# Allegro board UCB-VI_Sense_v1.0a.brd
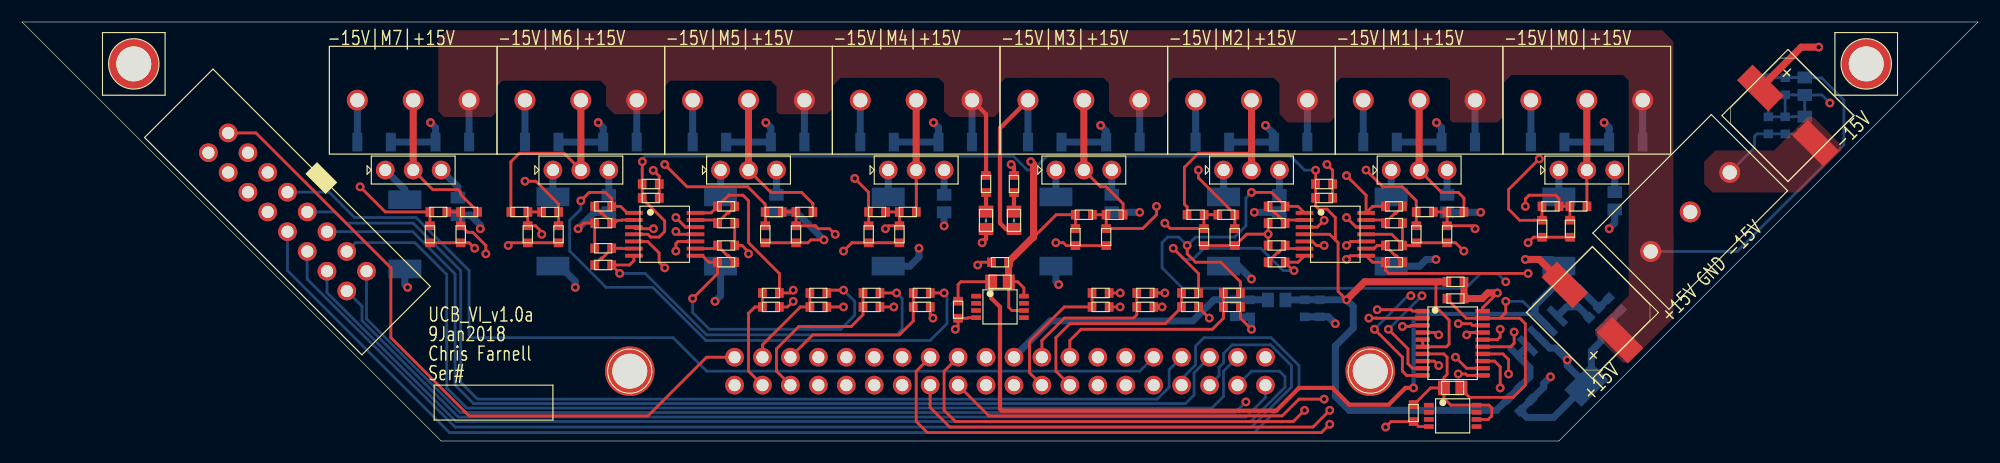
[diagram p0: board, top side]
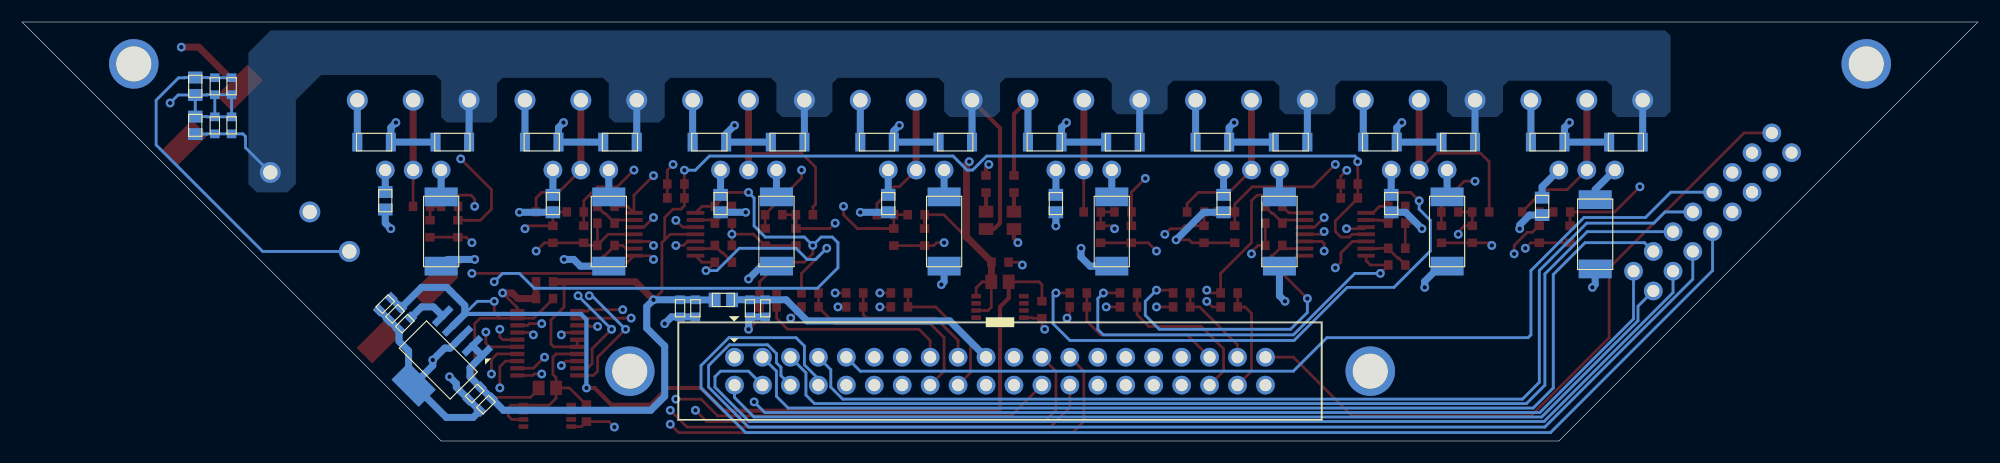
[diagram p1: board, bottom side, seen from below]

Outline 177.8 x 38.1 mm; copper layers: TOP, LAYER_2, LAYER_3, BOTTOM. Coordinates in mm from the lower left corner of the outline.
Outline path: 0,38.1 38.1,0 139.7,0 177.8,38.1 0,38.1

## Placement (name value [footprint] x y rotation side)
ADC1  AD7928BRUZ  [20-TSSOP]  130.05 8.89 0 top
C1  10uF  [C_1206]  145.8 27.18 180 bottom
C2  10uF  [C_1206]  130.56 27.18 180 bottom
C3  10uF  [C_1206]  115.32 27.18 180 bottom
C4  10uF  [C_1206]  100.08 27.18 180 bottom
C5  10uF  [C_1206]  84.84 27.18 180 bottom
C6  10uF  [C_1206]  69.6 27.18 180 bottom
C7  10uF  [C_1206]  54.36 27.18 180 bottom
C8  10uF  [C_1206]  39.12 27.18 180 bottom
C9  22uF  [C_0805]  162.05 32.26 270 bottom
C10  1uF  [C_0603]  160.27 32.26 270 bottom
C11  0.1uF  [C_0603]  158.75 32.26 270 bottom
C12  10uF  [C_1206]  138.68 27.18 180 bottom
C13  10uF  [C_1206]  123.44 27.18 180 bottom
C14  10uF  [C_1206]  108.2 27.18 180 bottom
C15  10uF  [C_1206]  92.96 27.18 180 bottom
C16  10uF  [C_1206]  77.72 27.18 180 bottom
C17  10uF  [C_1206]  62.48 27.18 180 bottom
C18  10uF  [C_1206]  47.24 27.18 180 bottom
C19  10uF  [C_1206]  32 27.18 180 bottom
C20  220uF  [EEE-FK-F]  142.75 11.68 135 top
C21  220uF  [EEE-FK-F]  160.53 29.59 315 top
C22  22uF  [C_0805]  162.05 28.7 270 bottom
C23  1uF  [C_0603]  160.27 28.7 270 bottom
C24  0.1uF  [C_0603]  158.75 28.7 270 bottom
C25  1uF  [C_0603]  110.24 12.06 270 bottom
C26  0.1uF  [C_0603]  111.63 12.06 270 bottom
C27  1uF  [C_0603]  116.59 12.06 270 bottom
C28  1uF  [C_0603]  85.09 11.94 270 top
C29  0.1uF  [C_0603]  117.98 12.06 270 bottom
C30  1uF  [C_0603]  88.9 16.26 0 top
C31  1uF  [C_0603]  135.64 3.3 315 bottom
C32  0.1uF  [C_0603]  136.65 4.32 315 bottom
C33  10nF  [C_0603]  143 10.67 315 bottom
C34  0.1uF  [C_0603]  143.89 11.56 315 bottom
C35  1uF  [C_0603]  144.78 12.45 315 bottom
C36  100pF  [C_0603]  140.72 19.3 90 top
C37  0.1uF  [C_0603]  138.18 19.3 270 top
C38  1uF  [C_0603]  130.3 14.48 0 top
C39  1uF  [C_0603]  130.3 12.95 0 top
C40  1uF  [C_0603]  126.49 2.54 90 top
C41  100pF  [C_0603]  129.54 18.8 90 top
C42  0.1uF  [C_0603]  126.75 18.8 270 top
C43  100pF  [C_0603]  107.44 18.54 90 top
C44  0.1uF  [C_0603]  110.24 18.54 270 top
C45  100pF  [C_0603]  98.55 18.54 90 top
C46  0.1uF  [C_0603]  95.76 18.54 270 top
C47  100pF  [C_0603]  79.76 18.8 90 top
C48  0.1uF  [C_0603]  76.96 18.8 270 top
C49  100pF  [C_0603]  70.36 18.8 90 top
C50  0.1uF  [C_0603]  67.56 18.8 270 top
C51  100pF  [C_0603]  45.97 18.8 90 top
C52  0.1uF  [C_0603]  48.77 18.8 270 top
C53  100pF  [C_0603]  39.88 18.8 90 top
C54  0.1uF  [C_0603]  37.08 18.8 270 top
C55  0.1uF  [C_0603]  118.36 22.1 0 top
C56  1uF  [C_0603]  118.36 23.37 0 top
C57  0.1uF  [C_0603]  57.15 22.1 0 top
C58  1uF  [C_0603]  57.15 23.37 0 top
D1  LED-G  [LED_0805-GREEN]  87.63 20.07 90 top
D2  LED-G  [LED_0805-GREEN]  90.17 20.07 90 top
J1  -  [1715734]  151.64 20.83 135 top
J3  SFH11-PBPC-D20-ST-BK  [40-IDC-F_MNT]  88.9 6.35 270 bottom
J4  AWHW 16G-0202-T  [16-IDC-M]  24.13 20.83 225 top
J5  -  [1715734]  142.24 30.99 270 top
J6  -  [1715734]  127 30.99 270 top
J7  -  [1715734]  111.76 30.99 270 top
J8  -  [1715734]  96.52 30.99 270 top
J9  -  [1715734]  81.28 30.99 270 top
J10  -  [1715734]  66.04 30.99 270 top
J11  -  [1715734]  50.8 30.99 270 top
J12  -  [1715734]  35.56 30.99 270 top
JP1  JP3  [J_1X3]  142.24 24.64 90 top
JP2  JP3  [J_1X3]  127 24.64 90 top
JP3  JP3  [J_1X3]  111.76 24.64 90 top
JP4  JP3  [J_1X3]  96.52 24.64 90 top
JP5  JP3  [J_1X3]  81.28 24.64 90 top
JP6  JP3  [J_1X3]  66.04 24.64 90 top
JP7  JP3  [J_1X3]  50.8 24.64 90 top
JP8  JP3  [J_1X3]  35.56 24.64 90 top
L1  220  [L_0805]  114.05 12.83 0 bottom
MECH1  Mech_Hole  [4-40_SCREW]  10.16 34.29 0 top
MECH2  Mech_Hole  [4-40_SCREW]  167.64 34.29 0 top
R1  6.19  [R_2512]  139.7 19.05 90 bottom
R3  1k  [R_0805]  88.9 14.48 0 top
R8  1k  [R_0805]  130.05 4.83 180 top
R9  200k  [R_0603]  141.48 21.34 180 top
R10  200k  [R_0603]  114.05 19.81 0 top
R11  100k  [R_0603]  138.94 21.34 0 top
R12  100k  [R_0603]  114.05 21.34 0 top
R13  2k  [R_0603]  87.63 23.37 270 top
R14  2k  [R_0603]  90.17 23.37 270 top
R15  10k  [R_0603]  109.98 13.46 180 top
R16  15k  [R_0603]  109.98 12.19 0 top
R17  10k  [R_0603]  106.17 13.46 180 top
R18  15k  [R_0603]  106.17 12.19 0 top
R19  200k  [R_0603]  130.3 20.83 180 top
R20  200k  [R_0603]  114.05 17.78 0 top
R21  100k  [R_0603]  127.51 20.83 0 top
R22  100k  [R_0603]  114.05 16.26 0 top
R23  10k  [R_0603]  102.11 13.46 180 top
R24  15k  [R_0603]  102.11 12.19 0 top
R25  200k  [R_0603]  106.68 20.57 0 top
R26  200k  [R_0603]  124.71 17.78 180 top
R27  100k  [R_0603]  109.47 20.57 180 top
R28  100k  [R_0603]  124.71 16.26 180 top
R29  10k  [R_0603]  98.04 13.46 180 top
R30  15k  [R_0603]  98.04 12.19 0 top
R31  200k  [R_0603]  99.31 20.57 180 top
R32  200k  [R_0603]  124.71 19.81 180 top
R33  100k  [R_0603]  96.52 20.57 0 top
R34  100k  [R_0603]  124.71 21.34 180 top
R35  10k  [R_0603]  81.79 13.46 180 top
R36  15k  [R_0603]  81.79 12.19 0 top
R37  200k  [R_0603]  80.52 20.83 180 top
R38  200k  [R_0603]  52.83 19.81 0 top
R39  100k  [R_0603]  77.72 20.83 0 top
R40  100k  [R_0603]  52.83 21.34 0 top
R41  10k  [R_0603]  77.22 13.46 180 top
R42  15k  [R_0603]  77.22 12.19 0 top
R43  200k  [R_0603]  71.12 20.83 180 top
R44  200k  [R_0603]  52.83 17.53 0 top
R45  100k  [R_0603]  68.33 20.83 0 top
R46  100k  [R_0603]  52.83 16 0 top
R47  10k  [R_0603]  72.39 13.46 180 top
R48  15k  [R_0603]  72.39 12.19 0 top
R49  200k  [R_0603]  45.21 20.83 0 top
R50  200k  [R_0603]  64.01 17.78 180 top
R51  100k  [R_0603]  48.01 20.83 180 top
R52  100k  [R_0603]  64.01 16.26 180 top
R53  10k  [R_0603]  68.07 13.46 180 top
R54  15k  [R_0603]  68.07 12.19 0 top
R55  200k  [R_0603]  40.64 20.83 180 top
R56  200k  [R_0603]  64.01 19.81 180 top
R57  100k  [R_0603]  37.85 20.83 0 top
R58  100k  [R_0603]  64.01 21.34 180 top
R59  6.19  [R_2512]  124.46 19.05 90 bottom
R61  6.19  [R_2512]  109.22 19.05 90 bottom
R63  6.19  [R_2512]  93.98 19.05 90 bottom
R65  6.19  [R_2512]  78.74 19.05 90 bottom
R67  6.19  [R_2512]  63.5 19.05 90 bottom
R69  6.19  [R_2512]  48.26 19.05 90 bottom
R71  6.19  [R_2512]  34.8 18.8 90 bottom
R72  140  [R_0805]  144.78 21.84 90 bottom
R73  140  [R_0805]  129.54 21.59 90 bottom
R74  140  [R_0805]  114.3 21.59 90 bottom
R75  140  [R_0805]  99.06 21.59 90 bottom
R76  140  [R_0805]  83.82 21.59 90 bottom
R77  140  [R_0805]  68.58 21.59 90 bottom
R78  140  [R_0805]  53.34 21.59 90 bottom
R79  140  [R_0805]  39.62 21.34 90 bottom
U1  LT1009CZ  [8-MSOP]  88.9 12.19 0 top
U2  TPS79533  [SOT-223-6]  139.95 7.37 135 bottom
U4  LT1009CZ  [8-MSOP]  130.05 2.29 0 top
U5  OPA4322AIPWR  [OPA4332_14-TSSOP]  119.38 18.8 0 top
U6  OPA4322AIPWR  [OPA4332_14-TSSOP]  58.42 18.8 0 top

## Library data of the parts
ADC1 = AD7928BRUZ
C1-C19 C22-C58 = CAP NP
C20 C21 = CAP P
D1 D2 = LED
J1 J5-J12 = Connector-3
J3 = Header_2x20
J4 = Header_2x8
JP1-JP8 = JP3
L1 = Ind
MECH1 MECH2 = Mech_Hole
R1 R3 R8-R59 R61 R63 R65 R67 R69 R71-R79 = R-Standard
U1 U4 = LT1009CZ
U2 = TPS795
U5 U6 = OPA4322AIPWR

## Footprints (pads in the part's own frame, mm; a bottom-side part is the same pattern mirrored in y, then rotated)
4-40_SCREW
  round 4.5 hole 3.175: 1(0,0)
8-MSOP
  rect 0.889x0.42 smd: 1(-2.17,0.975) 2(-2.17,0.325) 3(-2.17,-0.325) 4(-2.17,-0.975) 5(2.17,-0.975) 6(2.17,-0.325) 7(2.17,0.325) 8(2.17,0.975)
16-IDC-M
  round 1.7 hole 1.1: 1(-1.27,8.89) 2(1.27,8.89) 3(-1.27,6.35) 4(1.27,6.35) 5(-1.27,3.81) 6(1.27,3.81) 7(-1.27,1.27) 8(1.27,1.27) 9(-1.27,-1.27) 10(1.27,-1.27) 11(-1.27,-3.81) 12(1.27,-3.81) 13(-1.27,-6.35) 14(1.27,-6.35) 15(-1.27,-8.89) 16(1.27,-8.89)
20-TSSOP
  rect 1.3x0.4 smd: 1(-2.725,2.925) 2(-2.725,2.275) 3(-2.725,1.625) 4(-2.725,0.975) 5(-2.725,0.325) 6(-2.725,-0.325) 7(-2.725,-0.975) 8(-2.725,-1.625) 9(-2.725,-2.275) 10(-2.725,-2.925) 11(2.725,-2.925) 12(2.725,-2.275) 13(2.725,-1.625) 14(2.725,-0.975) 15(2.725,-0.325) 16(2.725,0.325) 17(2.725,0.975) 18(2.725,1.625) 19(2.725,2.275) 20(2.725,2.925)
40-IDC-F_MNT
  round 4.5 hole 3.175: (0,-33.655) (0,33.655)
  round 1.7 hole 1.1: 1(-1.27,-24.13) 2(1.27,-24.13) 3(-1.27,-21.59) 4(1.27,-21.59) 5(-1.27,-19.05) 6(1.27,-19.05) 7(-1.27,-16.51) 8(1.27,-16.51) 9(-1.27,-13.97) 10(1.27,-13.97) 11(-1.27,-11.43) 12(1.27,-11.43) 13(-1.27,-8.89) 14(1.27,-8.89) 15(-1.27,-6.35) 16(1.27,-6.35) 17(-1.27,-3.81) 18(1.27,-3.81) 19(-1.27,-1.27) 20(1.27,-1.27) 21(-1.27,1.27) 22(1.27,1.27) 23(-1.27,3.81) 24(1.27,3.81) 25(-1.27,6.35) 26(1.27,6.35) 27(-1.27,8.89) 28(1.27,8.89) 29(-1.27,11.43) 30(1.27,11.43) 31(-1.27,13.97) 32(1.27,13.97) 33(-1.27,16.51) 34(1.27,16.51) 35(-1.27,19.05) 36(1.27,19.05) 37(-1.27,21.59) 38(1.27,21.59) 39(-1.27,24.13) 40(1.27,24.13)
1715734
  round 1.9 hole 1.3: 1(0,5.08) 2(0,0) 3(0,-5.08)
C_0603
  rect 0.787x0.864 smd: 1(-0.775,0) 2(0.775,0)
C_0805
  rect 1.08x1.321 smd: 1(-0.794,0) 2(0.794,0)
C_1206
  rect 0.914x1.702 smd: 1(-1.524,0) 2(1.524,0)
EEE-FK-F
  rect 4x2 smd: 1(-3.55,0) 2(3.55,0)
J_1X3
  round 1.7 hole 1.1: 1(0,2.54) 2(0,0) 3(0,-2.54)
L_0805
  rect 1.08x1.321 smd: 1(-0.794,0) 2(0.794,0)
LED_0805-GREEN
  rect 1.08x1.321 smd: 1(-0.794,0) 2(0.794,0)
OPA4332_14-TSSOP
  rect 1.6x0.35 smd: 1(-2.8,1.95) 2(-2.8,1.3) 3(-2.8,0.65) 4(-2.8,0) 5(-2.8,-0.65) 6(-2.8,-1.3) 7(-2.8,-1.95) 8(2.8,-1.95) 9(2.8,-1.3) 10(2.8,-0.65) 11(2.8,0) 12(2.8,0.65) 13(2.8,1.3) 14(2.8,1.95)
R_0603
  rect 0.787x0.864 smd: 1(-0.775,0) 2(0.775,0)
R_0805
  rect 1.08x1.321 smd: 1(-0.794,0) 2(0.794,0)
R_2512
  rect 1.7x3 smd: 1(-3.15,0) 2(3.15,0)
SOT-223-6
  rect 2.2x0.6 smd: 1(3.1,-2.54) 2(3.1,-1.27) 3(3.1,0) 4(3.1,1.27) 5(3.1,2.54)
  rect 2.2x3.5 smd: 6(-3.175,0)

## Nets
2V5_REF: C30.2 C37.1 C42.1 C44.1 C46.1 C48.1 C50.1 C52.1 C54.1 R3.2 R11.1 R21.1 R27.1 R33.1 R39.1 R45.1 R51.1 R57.1 U1.6(V+.) U1.8(V+)
3V3: ADC1.19(VDRIVE) C28.1 C34.1 C35.1 C39.1 R3.1 R8.1 U2.4(VOUT)
5V0: ADC1.5(AVDD) ADC1.6(AVDD.) C27.1 C29.1 C31.1 C32.1 C38.1 C55.1 C56.1 C57.1 C58.1 L1.2 U2.1(EN) U2.2(VIN) U5.4(V+) U6.4(V+)
5V_IDC: C25.1 C26.1 J3.19 J3.39 J4.15 L1.1
+15V: C1.1 C2.1 C3.1 C4.1 C5.1 C6.1 C7.1 C8.1 C9.1 C10.1 C11.1 C20.1 J1.1(P1) J5.1(P1) J6.1(P1) J7.1(P1) J8.1(P1) J9.1(P1) J10.1(P1) J11.1(P1) J12.1(P1) R13.1
-15V: C12.2 C13.2 C14.2 C15.2 C16.2 C17.2 C18.2 C19.2 C21.2 C22.2 C23.2 C24.2 D2.1(CATHODE) J1.3(P3) J5.3(P3) J6.3(P3) J7.3(P3) J8.3(P3) J9.3(P3) J10.3(P3) J11.3(P3) J12.3(P3)
GND: ADC1.4(AGND) ADC1.8(AGND.) ADC1.17(AGND..) ADC1.20(AGND...) C1.2 C2.2 C3.2 C4.2 C5.2 C6.2 C7.2 C8.2 C9.2 C10.2 C11.2 C12.1 C13.1 C14.1 C15.1 C16.1 C17.1 C18.1 C19.1 C20.2 C21.1 C22.1 C23.1 C24.1 C25.2 C26.2 C27.2 C28.2 C29.2 C30.1 C31.2 C32.2 C33.2 C34.2 C35.2 C36.1 C37.2 C38.2 C39.2 C40.1 C41.1 C42.2 C43.1 C44.2 C45.1 C46.2 C47.1 C48.2 C49.1 C50.2 C51.1 C52.2 C53.1 C54.2 C55.2 C56.2 C57.2 C58.2 D1.1(CATHODE) J1.2(P2) J3.20 J3.40 J4.16 R1.1 R10.1 R14.1 R16.2 R18.2 R20.1 R24.2 R26.1 R30.2 R32.1 R36.2 R38.1 R42.2 R44.1 R48.2 R50.1 R54.2 R56.1 R59.1 R61.1 R63.1 R65.1 R67.1 R69.1 R71.1 R72.1 R73.1 R74.1 R75.1 R76.1 R77.1 R78.1 R79.1 U1.4(GND) U2.3(GND) U2.6(GND.) U4.4(GND) U5.11(V-) U6.11(V-)
IDC_ADC-0: J3.15 R15.2 R16.1
IDC_ADC-1: J3.16 R17.2 R18.1
IDC_ADC-2: J3.17 R23.2 R24.1
IDC_ADC-3: J3.18 R29.2 R30.1
IDC_ADC-4: J3.35 R35.2 R36.1
IDC_ADC-5: J3.36 R41.2 R42.1
IDC_ADC-6: J3.37 R47.2 R48.1
IDC_ADC-7: J3.38 R53.2 R54.1
IDC_IO-1: J3.1 J4.1
IDC_IO-2: J3.2 J4.2
IDC_IO-3: J3.3 J4.3
IDC_IO-4: J3.4 J4.4
IDC_IO-5: J3.5 J4.5
IDC_IO-6: J3.6 J4.6
IDC_IO-7: J3.7 J4.7
IDC_IO-8: J3.8 J4.8
IDC_IO-9: J3.9 J4.9
IDC_IO-10: J3.10 J4.10
IDC_IO-11: J3.11 J4.11
IDC_IO-12: J3.12 J4.12
IDC_IO-13: J3.13 J4.13
IDC_IO-14: J3.14 J4.14
MEA_0: J5.2(P2) JP1.2 R9.1
MEA_1: J6.2(P2) JP2.2 R19.1
MEA_2: J7.2(P2) JP3.2 R25.1
MEA_3: J8.2(P2) JP4.2 R31.1
MEA_4: J9.2(P2) JP5.2 R37.1
MEA_5: J10.2(P2) JP6.2 R43.1
MEA_6: J11.2(P2) JP7.2 R49.1
MEA_7: J12.2(P2) JP8.2 R55.1
SPI-ADC_5V-CH0: ADC1.16(VIN0) R12.2 R15.1 U5.1(OUT)
SPI-ADC_5V-CH1: ADC1.15(VIN1) R17.1 R22.2 U5.7(OUT)
SPI-ADC_5V-CH2: ADC1.14(VIN2) R23.1 R28.2 U5.8(OUT)
SPI-ADC_5V-CH3: ADC1.13(VIN3) R29.1 R34.2 U5.14(OUT)
SPI-ADC_5V-CH4: ADC1.12(VIN4) R35.1 R40.2 U6.1(OUT)
SPI-ADC_5V-CH5: ADC1.11(VIN5) R41.1 R46.2 U6.7(OUT)
SPI-ADC_5V-CH6: ADC1.10(VIN6) R47.1 R52.2 U6.8(OUT)
SPI-ADC_5V-CH7: ADC1.9(VIN7) R53.1 R58.2 U6.14(OUT)
SPI-ADC_CS: ADC1.3(CS) J3.24
SPI-ADC_DIN: ADC1.2(DIN) J3.25
SPI-ADC_DOUT: ADC1.18(DOUT) J3.26
SPI-ADC_SCLK: ADC1.1(SCLK) J3.23
N365232: ADC1.7(REF_IN) C40.2 R8.2 U4.6(V+.) U4.8(V+)
N367140: C36.2 R9.2 R11.2 U5.3(+IN)
N367168: R10.2 R12.1 U5.2(-IN)
N370101: C33.1 U2.5(NR/FB)
N387715: JP1.1 R1.2
N388314: JP1.3 R72.2
N392987: D2.2(ANODE) R14.2
N392991: D1.2(ANODE) R13.2
N402358: C41.2 R19.2 R21.2 U5.5(+IN)
N402362: R20.2 R22.1 U5.6(-IN)
N403154: C43.2 R25.2 R27.2 U5.10(+IN)
N403158: R26.2 R28.1 U5.9(-IN)
N403978: C45.2 R31.2 R33.2 U5.12(+IN)
N403982: R32.2 R34.1 U5.13(-IN)
N404826: C47.2 R37.2 R39.2 U6.3(+IN)
N404830: R38.2 R40.1 U6.2(-IN)
N405710: C49.2 R43.2 R45.2 U6.5(+IN)
N405714: R44.2 R46.1 U6.6(-IN)
N406610: C51.2 R49.2 R51.2 U6.10(+IN)
N406614: R50.2 R52.1 U6.9(-IN)
N407827: C53.2 R55.2 R57.2 U6.12(+IN)
N407831: R56.2 R58.1 U6.13(-IN)
N416291: JP2.1 R59.2
N416303: JP2.3 R73.2
N416911: JP3.1 R61.2
N416923: JP3.3 R74.2
N417886: JP4.1 R63.2
N417898: JP4.3 R75.2
N420263: JP5.1 R65.2
N420287: JP5.3 R76.2
N420898: JP6.1 R67.2
N420922: JP6.3 R77.2
N421540: JP7.1 R69.2
N421564: JP7.3 R78.2
N422187: JP8.1 R71.2
N422211: JP8.3 R79.2

Pads without a net: J3 21 22 27 28 29 30 31 32 33 34; MECH1 1; MECH2 1; U1 1 2 3 5 7; U4 1 2 3 5 7

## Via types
v1: diameter 0.8, hole 0.4, TOP to BOTTOM, 122 vias

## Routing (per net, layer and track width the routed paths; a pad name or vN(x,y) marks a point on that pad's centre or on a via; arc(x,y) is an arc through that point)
2V5_REF: length 204.1
  TOP w0.254: 91.95,18.52 94.01,20.57 R33.1 95.76,20.56 C46.1 ; C54.1 37.08,20.82 R57.1 33.02,20.83 v1(30.73,23.11) ; C48.1 76.96,20.82 R39.1 76.95,22.62 v1(75.69,23.88) ; U1.8 91.07,13.92 90.51,14.48 R3.2 89.69,12.16 89.99,11.87 U1.6 ; C50.1 67.56,20.82 R45.1 67.55,21.54 65.98,23.11 60.45,23.11 v1(58.42,25.15) ; C52.1 48.78,19.58 R51.1 48.78,21.54 46.7,23.62 v1(45.72,23.62) ; C42.1 126.75,20.82 R21.1 126.73,21.86 125.48,23.11 123.7,23.11 v1(122.17,24.64) ; R11.1 138.16,20.09 C37.1 137.46,20.08 137.45,20.07 136.14,20.07 135.13,21.08 135.13,22.86 v1(137.92,25.65) ; v1(106.93,24.64) 106.93,23.93 110.25,20.61 R27.1 110.25,19.33 C44.1
  TOP w0.635: R3.2 89.67,14.5 C30.2 89.67,16.29 91.9,18.52 91.95,18.52 91.95,25.15 v1(91.69,25.4)
  LAYER_3 w0.254: v1(45.72,23.62) 45.72,26.67 ; v1(75.69,23.88) 75.69,26.67 ; 57.66,26.67 57.66,25.91 v1(58.42,25.15) ; v1(122.17,24.64) 122.17,26.67 ; v1(106.93,24.64) 106.93,26.67
  LAYER_3 w0.635: v1(137.92,25.65) 136.91,26.67 92.96,26.67 v1(91.69,25.4) 90.42,26.67 32.51,26.67 30.73,24.89 v1(30.73,23.11)
3V3: length 109.9
  TOP w0.254: R8.1 130.84,4.71 131.58,3.97 135.54,3.97 136.65,5.08 136.65,10.67 136.15,11.17 134.38,11.17 ; 134.38,11.17 134.38,11.19 134.87,11.68 v1(134.87,12.7) ; 134.38,11.17 ADC1.19 131.28,11.17 129.53,12.92 C39.1 ; R3.1 85.34,14.48 85.09,14.22 C28.1
  TOP w0.381: R3.1 88.11,12.99 88.9,12.19 88.9,2.92 89.07,2.76 114.01,2.76 116.08,4.83 119.13,4.83 120.65,3.3 124.22,3.3 125.75,4.83 v1(126.49,4.83)
  BOTTOM w0.254: 137.55,11.57 136.42,12.7 v1(134.87,12.7)
  BOTTOM w0.381: 137.55,11.55 127,11.55 126.49,11.05 v1(126.49,4.83)
  BOTTOM w0.635: C35.1 C34.1 141.48,13.97 139.19,13.97 137.55,12.33 137.55,11.55 138.65,10.46 U2.4
5V0: length 147.5
  TOP w0.254: v1(56.39,25.4) 56.39,24.72 56.38,24.71 C58.1 C57.1 56.38,22.06 58.42,20.01 58.42,19.05 57.91,18.54 57.15,18.54 56.9,18.8 U6.4 ; 119.38,18.29 119.63,18.03 119.63,13.6 v1(120.4,12.84) ; 119.38,18.29 119.38,20.32 118.62,21.08 117.89,21.08 117.59,21.39 C55.1 C56.1 v1(117.59,24.63) ; 119.38,18.29 118.87,18.8 U5.4 ; ADC1.5 ADC1.6 129.47,8.56 129.72,8.82 129.72,10.99 128.52,12.19 128.52,14.22 128.78,14.48
  TOP w0.635: v1(120.4,12.84) 122.03,14.48 C38.1
  BOTTOM w0.254: v1(56.39,25.4) 56.39,25.65 56.64,25.91 90.12,25.91 91.39,24.64 91.89,24.64 93.16,25.91 115.32,25.91 116.6,24.63 v1(117.59,24.63)
  BOTTOM w0.635: U2.2 U2.1 137.08,6.65 137.08,5.84 C32.1 C31.1 134.03,2.79 120.65,2.79 119.38,4.06 119.38,8.64 121.01,10.27 121.01,12.22 v1(120.4,12.84) C29.1 C27.1 116.57,12.83 L1.2
5V_IDC: length 122.3
  TOP w0.254: J4.15 21.26,28.01 33.53,15.75 33.53,9.4 40.64,2.29 56.9,2.29 62.23,7.62 J3.39
  LAYER_3 w0.254: J3.19 89.04,6.49 89.04,3.7 88.54,3.2 64.62,3.2 63.5,4.32 63.5,6.35 J3.39
  BOTTOM w0.635: L1.1 113.24,12.84 C26.1 C25.1 108.34,12.84 106.43,10.92 93.47,10.92 J3.19
+15V: length 71.2
  TOP w0.381: R13.1 87.63,29.72 J9.1
  BOTTOM w0.254: J1.1 155.92,17.24 165.61,26.92 165.61,30.99 163.58,33.02 163.02,33.02 162.99,33.05 C9.1 161,33.05 160.99,33.03 C10.1 C11.1
  BOTTOM w0.635: C4.1 J8.1 ; C2.1 J6.1 ; C8.1 J12.1 ; C3.1 J7.1 ; C1.1 J5.1 ; C5.1 J9.1 ; C6.1 J10.1 ; C7.1 J11.1
-15V: length 53.1
  TOP w0.381: J8.3 88.9,28.45 88.9,19.81 89.44,19.27 D2.1
  BOTTOM w0.254: C22.2 161,27.91 160.99,27.93 C23.2 C24.2 157.72,27.93 157.48,27.69 157.48,26.67 J1.3
  BOTTOM w0.635: C17.2 J10.3 ; C15.2 J8.3 ; C16.2 J9.3 ; C13.2 J6.3 ; C19.2 J12.3 ; C12.2 J5.3 ; C14.2 J7.3 ; C18.2 J11.3
GND: length 251.5
  TOP w0.254: v1(82.8,11.18) 82.56,11.42 R36.2 ; v1(72.9,18.29) 71.71,18.29 71.44,18.02 C49.1 C50.2 ; v1(118.62,25.15) 119.14,24.63 C56.2 C55.2 ; v1(74.68,17.27) 75.43,18.02 C48.2 C47.1 ; v1(111.76,10.16) 110.76,11.16 R16.2 ; U5.11 124.51,18.8 125.49,17.82 ; R20.1 v1(113.27,18.81) ; v1(113.27,18.81) 111.32,18.81 110.27,17.77 C44.2 C43.1 ; v1(113.27,18.81) R10.1 ; C54.2 C53.1 40.65,18.02 v1(41.15,17.53) ; R18.2 106.95,12.15 v1(107.92,11.18) ; ADC1.20 132.77,12.12 v1(134.11,13.46) ; v1(131.06,17.27) 130.31,18.02 C41.1 C42.2 126.5,17.78 R26.1 125.49,17.82 ; v1(66.04,17.02) 66.04,17.2 65.46,17.78 R50.1 R56.1 ; R42.2 v1(79.25,12.19) ; U6.11 59.69,18.8 v1(59.44,19.05) ; C45.1 C46.2 94.93,17.77 94.66,18.03 v1(93.98,18.03) ; C36.1 C37.2 137.4,18.53 v1(136.91,18.03) ; v1(128.78,9.65) 128.56,9.87 ADC1.4 ; v1(50.55,19.3) 51.05,19.81 R38.1 R44.1 ; 125.49,17.82 R32.1 ; C30.1 87.12,16.26 v1(86.87,16) ; v1(44.2,17.78) 44.44,18.02 C51.1 C52.2 ; R24.2 v1(103.63,12.19) ; C57.2 C58.2 57.92,24.08 57.39,24.61 v1(57.38,24.61) ; U1.4 86.01,11.22 85.95,11.16 C28.2 85.09,10.41 v1(84.84,10.16) ; R48.2 v1(74.68,12.19) ; ADC1.17 131.53,9.87 v1(131.32,9.65) ; R54.2 69.6,12.19 v1(70.1,12.7) ; U4.4 126.95,1.31 C40.1 124.45,1.77 v1(123.95,1.27) ; v1(128.78,6.86) 128.37,7.26 ADC1.8 ; R30.2 v1(99.82,12.19)
  TOP w0.381: v1(87.27,18.03) 87.63,18.39 D1.1 ; v1(89.92,25.15) 90.17,24.89 R14.1
  TOP w0.635: C38.2 C39.2 132.73,12.95 133.24,13.46 v1(134.11,13.46) ; C21.1 161.73,35.81 v1(163.32,35.81) ; v1(136.65,16.51) 137.92,16.51 C20.2
  BOTTOM w0.254: v1(164.34,30.73) 163.61,31.46 C9.2 ; C23.1 C24.1 C11.2 C10.2 ; C23.1 C10.2 ; C23.1 160.99,29.48 161,29.5 C22.1 C9.2 ; C9.2 161,31.46 160.99,31.48 C10.2
  BOTTOM w0.635: v1(94.23,14.22) 93.98,14.48 R63.1 ; v1(82.86,28.96) 83.31,28.5 C5.2 C16.1 ; v1(138.94,5.84) 138.32,5.23 138.32,4.89 C32.2 C31.2 136.79,2.14 139.22,2.14 U2.6 ; R76.1 v1(83.82,19.56) ; C27.2 C29.2 118.76,11.29 v1(119.38,10.67) ; R1.1 139.09,16.51 v1(136.65,16.51) ; R73.1 v1(132.59,20.8) ; R78.1 52.04,20.8 v1(50.55,19.3) ; R59.1 127.04,15.9 127.65,16.51 v1(128.52,16.51) ; v1(52.38,28.96) 52.83,28.5 C7.2 C18.1 ; v1(98.04,28.7) 98.55,28.19 C4.2 C15.1 ; v1(111.76,14.73) 110.59,15.9 R61.1 ; v1(143.82,28.96) 144.27,28.5 C1.2 C12.1 ; R67.1 63.5,13.21 v1(62.99,12.7) ; v1(37.14,28.96) 37.59,28.5 C8.2 C19.1 ; C35.2 C34.2 C33.2 143.52,10.09 143.52,9.07 142.66,8.2 142.66,5.58 U2.6 ; R77.1 70.39,20.8 v1(72.9,18.29) ; v1(50.29,13.97) 50.29,14.52 48.91,15.9 R69.1 ; R72.1 144.78,19.81 v1(144.27,19.3) ; v1(128.58,28.96) 129.03,28.5 C2.2 C13.1 ; v1(81.53,17.53) 81.53,16.72 80.71,15.9 R65.1 ; U2.6 140.46,6.86 v1(140.46,7.37) 139.38,8.45 138.87,8.45 U2.3 ; R75.1 v1(101.6,20.8) ; v1(41.66,19.3) 41.66,19.64 40.75,20.54 R79.1 ; v1(67.62,28.96) 68.07,28.5 C6.2 C17.1 ; C14.1 C3.2 113.79,27.94 v1(113.03,28.7) ; C25.2 C26.2 111.76,11.16 v1(111.76,10.16) ; R74.1 v1(112.01,20.8) ; R71.1 34.8,14.22 v1(35.05,13.97)
IDC_ADC-0: length 18.6
  TOP w0.254: J3.15 95.25,9.14 96.27,10.16 108.2,10.16 109.21,11.16 R16.1 R15.2
IDC_ADC-1: length 18.7
  TOP w0.254: R17.2 R18.1 105.4,12.15 103.91,10.67 95.25,10.67 93.98,9.4 93.98,6.35 J3.16
IDC_ADC-2: length 13.1
  TOP w0.254: J3.17 92.71,9.14 94.74,11.18 101.03,11.18 101.33,11.48 R24.1 R23.2
IDC_ADC-3: length 12.7
  TOP w0.254: R29.2 R30.1 94.74,12.19 91.58,9.03 91.58,6.21 J3.18
IDC_ADC-4: length 15.1
  TOP w0.254: R35.2 R36.1 81.01,10.91 79.76,9.65 71.88,9.65 J3.35
IDC_ADC-5: length 15
  TOP w0.254: J3.36 68.58,6.35 68.58,8.38 70.61,10.41 75.37,10.41 76.44,11.48 R42.1 R41.2
IDC_ADC-6: length 8.1
  TOP w0.254: R47.2 R48.1 70.75,12.19 67.31,8.75 J3.37
IDC_ADC-7: length 9.8
  TOP w0.254: J3.38 66.04,6.35 66.04,11.61 66.62,12.19 R54.1 R53.2
IDC_IO-1: length 93
  LAYER_3 w0.254: v1(111.25,3.56) 111.76,4.06 111.76,6.35 J3.1
  BOTTOM w0.254: v1(111.25,3.56) 110.29,2.59 39.83,2.59 31.31,11.1 J4.1
IDC_IO-2: length 90.9
  BOTTOM w0.254: J4.2 30.91,12.25 30.91,10.94 39.66,2.18 111.26,2.18 113.03,3.95 J3.2
IDC_IO-3: length 96.8
  BOTTOM w0.254: J3.3 109.22,6.35 109.22,4.06 108.15,3 40.44,3 38.61,4.83 38.61,15.14 35.71,18.03 30.32,18.03 J4.3
IDC_IO-4: length 101.2
  BOTTOM w0.254: J4.4 27.72,13.49 39.44,1.78 111.69,1.78 114.81,4.89 114.81,5.84 114.3,6.35 111.76,6.35 J3.4
IDC_IO-5: length 95.6
  BOTTOM w0.254: J3.5 106.54,6.21 106.54,4.18 105.77,3.4 41.05,3.4 39.37,5.08 39.37,15.19 35.53,19.03 J4.5
IDC_IO-6: length 111.7
  BOTTOM w0.254: J3.6 108.81,5.94 108.81,6.71 109.22,7.11 109.22,7.95 110.02,8.75 113.5,8.75 115.39,6.86 115.39,4.9 111.76,1.27 39.37,1.27 25.93,14.71 J4.6
IDC_IO-7: length 95
  BOTTOM w0.254: J3.7 104.28,6.49 104.28,4.89 103.2,3.81 41.4,3.81 39.88,5.33 39.88,15.49 35.56,19.81 29.46,19.81 28.45,20.83 J4.7
IDC_IO-8: length 120.2
  BOTTOM w0.254: J3.8 105.41,5.65 106.68,6.92 106.68,8.64 107.44,9.4 113.54,9.4 116.08,6.86 116.08,4.83 112.01,0.76 38.86,0.76 24.13,15.49 J4.8
IDC_IO-9: length 89.4
  BOTTOM w0.254: J4.9 27.92,22.62 30.23,20.32 35.81,20.32 40.64,15.49 40.64,9.65 40.89,9.4 59.18,9.4 62.23,6.35 101.6,6.35 J3.9
IDC_IO-10: length 90.3
  LAYER_3 w0.254: J3.10 100.08,2.29 39.28,2.29 22.33,19.23 J4.10
IDC_IO-11: length 96.4
  LAYER_3 w0.254: J3.11 100.33,6.68 99.2,5.55 99.2,3.7 98.3,2.79 40.39,2.79 37.59,5.59 37.59,13.72 25.65,25.65 23.57,25.65 J4.11
IDC_IO-12: length 101
  LAYER_3 w0.254: J4.12 20.54,20.36 39.12,1.78 102.11,1.78 104.14,3.81 104.14,5.84 103.63,6.35 101.6,6.35 J3.12
IDC_IO-13: length 127
  LAYER_3 w0.254: J4.13 18.85,26.22 17.02,24.38 17.02,22.61 38.86,0.76 105.92,0.76 109.22,4.06 109.22,8.89 108.46,9.65 98.3,9.65 97.79,9.14 J3.13
IDC_IO-14: length 116.8
  LAYER_3 w0.254: J3.14 99.2,6.49 99.2,8.52 99.82,9.14 106.17,9.14 106.68,8.64 106.68,4.32 103.63,1.27 38.93,1.27 18.74,21.46 J4.14
MEA_0: length 9.7
  TOP w0.254: JP1.2 142.24,23.51 142.25,23.5 R9.1
  TOP w0.635: J5.2 JP1.2
MEA_1: length 12.7
  TOP w0.254: JP2.2 129.03,22.61 130.56,22.61 131.08,22.09 R19.1
  TOP w0.635: J6.2 JP2.2
MEA_2: length 17.6
  TOP w0.254: 111.76,25.77 111.37,26.16 106.93,26.16 105.66,24.89 105.66,21.53 105.91,21.29 R25.1
  TOP w0.635: J7.2 JP3.2
MEA_3: length 12.2
  TOP w0.254: R31.1 100.09,21.58 98.55,23.11 98.04,23.11 JP4.2
  TOP w0.635: J8.2 JP4.2
MEA_4: length 10.2
  TOP w0.254: R37.1 81.29,23.5 81.28,23.51 JP5.2
  TOP w0.635: J9.2 JP5.2
MEA_5: length 14.2
  TOP w0.254: R43.1 71.89,21.54 71.88,21.55 71.88,21.59 70.87,22.61 68.07,22.61 JP6.2
  TOP w0.635: J10.2 JP6.2
MEA_6: length 18.2
  TOP w0.254: JP7.2 49.28,26.16 45.21,26.16 44.44,25.39 R49.1
  TOP w0.635: J11.2 JP7.2
MEA_7: length 13.9
  TOP w0.254: R55.1 41.41,20.87 39.88,22.4 39.88,22.61 39.62,22.86 37.34,22.86 JP8.2
  TOP w0.635: J12.2 JP8.2
SPI-ADC_5V-CH0: length 68.3
  TOP w0.254: v1(134.37,10.16) 134.37,9.47 134.11,9.22 ADC1.16 ; R15.1 110.76,14.17 110.74,14.19 110.74,14.48 108.97,16.26 106.68,16.26 105.92,17.02 v1(105.92,17.78) ; U5.1 115.99,21.34 R12.2 114.82,21.37 113.59,22.61 v1(111.76,22.61)
  LAYER_3 w0.254: v1(134.37,10.16) 135.89,11.68 135.89,12.78 134.87,13.8 v1(134.87,14.48)
  BOTTOM w0.254: v1(134.87,14.48) 134.11,15.24 132.59,15.24 131.24,13.89 105.49,13.89 103.63,15.75 103.63,18.03 104.14,18.54 105.16,18.54 v1(105.92,17.78) 106.68,18.54 110.24,18.54 111.25,19.56 111.25,22.1 v1(111.76,22.61)
SPI-ADC_5V-CH1: length 50.8
  TOP w0.254: v1(135.64,9.91) 135.64,8.89 135.31,8.56 ADC1.15 ; R17.1 106.95,15.23 v1(104.65,17.53) ; U5.7 115.99,16.26 R22.2 114.82,16.22 115.54,15.49 v1(115.63,15.49)
  LAYER_3 w0.254: v1(115.63,15.49) 135.13,15.49 136.4,14.22 136.4,10.67 v1(135.64,9.91)
  BOTTOM w0.254: v1(104.65,17.53) 105.66,16.51 106.43,16.51 107.44,17.53 112.6,17.53 114.64,15.49 v1(115.63,15.49)
SPI-ADC_5V-CH2: length 51.8
  TOP w0.254: v1(103.89,13.46) R23.1 ; v1(136.91,15.24) 124.24,15.24 123.94,15.54 R28.2 122.77,16.26 U5.8 120.73,16.85 v1(120.4,16.51) ; ADC1.14 134.62,7.91 135.13,7.41 v1(135.13,6.1)
  LAYER_3 w0.254: v1(136.91,15.24) 136.91,7.87 v1(135.13,6.1) ; v1(120.4,16.51) 104.39,16.51 103.89,16 v1(103.89,13.46)
SPI-ADC_5V-CH3: length 77.4
  TOP w0.254: v1(134.37,4.83) 134.37,6.76 133.86,7.26 ADC1.13 ; v1(120.4,24.13) 122.18,22.35 U5.14 122.77,21.34 R34.2 ; v1(99.82,13.46) R29.1
  LAYER_3 w0.254: v1(99.82,13.46) 99.82,20.57 102.53,23.29 118.28,23.29 119.13,24.13 v1(120.4,24.13) 121.67,22.86 136.91,22.86 137.92,21.84 137.92,7.7 135.05,4.83 v1(134.37,4.83)
SPI-ADC_5V-CH4: length 108.8
  TOP w0.254: U6.1 54.99,20.75 54.4,21.34 R40.2 53.61,22.05 53.05,22.61 51.56,22.61 v1(50.8,21.84) ; ADC1.12 131.31,6.61 v1(130.3,7.62) ; v1(83.82,13.46) R35.1
  LAYER_3 w0.254: v1(130.3,7.62) 129.54,7.62 123.29,13.87 119.28,13.87 116.08,10.67 112.21,10.67 112.04,10.84 111.48,10.84 110.73,10.09 87.19,10.09 v1(83.82,13.46)
  BOTTOM w0.254: v1(83.82,13.46) 84.07,13.21 84.07,10.67 82.55,9.14 62.16,9.14 57.34,13.97 53.09,13.97 49.78,17.27 49.78,20.07 50.8,21.08 v1(50.8,21.84)
SPI-ADC_5V-CH5: length 99.7
  TOP w0.254: v1(130.56,6.1) 131.24,6.1 131.37,5.96 ADC1.11 ; v1(54.33,15.24) 53.61,15.96 R46.2 55.23,16 55.62,16.39 U6.7 ; v1(79.5,13.46) R41.1
  LAYER_3 w0.254: v1(130.56,6.1) 131.32,6.86 131.32,8.38 129.03,10.67 127.25,10.67 123.65,14.27 118.92,14.27 116.33,11.68 111.25,11.68 110.06,10.5 88.06,10.5 84.07,14.48 80.52,14.48 v1(79.5,13.46)
  BOTTOM w0.254: v1(54.33,15.24) 56.64,15.24 62.23,9.65 79.5,9.65 80.01,10.16 80.01,12.95 v1(79.5,13.46)
SPI-ADC_5V-CH6: length 95.4
  TOP w0.254: v1(74.68,13.72) 73.42,13.72 R47.1 ; ADC1.10 125.86,5.96 125.48,6.35 125.48,7.62 v1(122.94,10.16) ; U6.8 61.85,16.85 62.44,16.26 R52.2 63.23,15.23 v1(60.96,12.95)
  LAYER_3 w0.254: v1(74.68,13.72) 75.95,14.99 84.33,14.99 88.39,10.92 106.17,10.92 107.44,12.19 116.08,12.19 118.57,14.68 124.76,14.68 v1(126.24,13.21)
  BOTTOM w0.254: v1(60.96,12.95) 60.96,11.68 62.48,10.16 74.42,10.16 75.69,11.43 75.69,12.7 v1(74.68,13.72) ; v1(126.24,13.21) 125.98,13.21 v1(122.94,10.16)
SPI-ADC_5V-CH7: length 88.2
  TOP w0.254: ADC1.9 126.39,6.61 125.98,7.02 125.98,8.38 v1(124.21,10.16) ; v1(70.1,13.72) 69.85,13.46 R53.1 68.85,15.23 66.04,18.03 66.04,21.84 65.53,22.35 64.25,22.35 63.86,21.97 63.82,21.97 63.23,21.37 R58.2 62.64,20.75 U6.14
  LAYER_3 w0.254: v1(127.25,13.21) 125.37,15.09 118.21,15.09 115.82,12.7 107.19,12.7 105.92,11.43 88.65,11.43 84.58,15.49 71.88,15.49 v1(70.1,13.72)
  BOTTOM w0.254: v1(127.25,13.21) v1(124.21,10.16)
SPI-ADC_CS: length 50.4
  TOP w0.254: ADC1.3 126.26,10.52 126.16,10.41 v1(125.48,10.41) ; v1(118.36,3.81) 116.08,3.81 114.55,2.29 87.88,2.29 J3.24
  LAYER_3 w0.254: v1(125.48,10.41) 125.48,4.57 124.46,3.56 119.89,3.56 119.63,3.81 v1(118.36,3.81)
SPI-ADC_DIN: length 64.7
  TOP w0.254: v1(118.87,1.52) 118.11,0.76 82.3,0.76 81.28,1.78 81.28,6.35 J3.25 ; ADC1.2 123.12,11.17 123.11,11.18 v1(122.43,11.18)
  LAYER_3 w0.254: v1(122.43,11.18) 121.49,11.18 121.32,11.35 118.28,11.35 117.35,10.41 117.35,3.05 v1(118.87,1.52)
SPI-ADC_DOUT: length 64.2
  TOP w0.254: v1(118.87,2.79) 117.35,1.27 84.33,1.27 82.55,3.05 J3.26 ; ADC1.18 131.84,10.52 131.69,10.67 v1(130.56,10.67)
  LAYER_3 w0.254: v1(130.56,10.67) 132.08,10.67 132.33,10.41 132.33,4.06 132.08,3.81 125.73,3.81 124.71,2.79 v1(118.87,2.79)
SPI-ADC_SCLK: length 58
  TOP w0.254: J3.23 83.82,6.35 83.82,2.79 84.84,1.78 115.57,1.78 v1(116.59,2.79) ; v1(123.19,11.94) 126.27,11.94 126.39,11.82 ADC1.1
  LAYER_3 w0.254: v1(123.19,11.94) 118.11,11.94 116.59,10.41 v1(116.59,2.79)
N365232: length 16.5
  TOP w0.254: R8.2 128.04,4.83 126.53,3.31 C40.2 ; R8.2 129.25,5.77 129.54,6.05 129.54,7.62 129.25,7.91 ADC1.7 ; R8.2 129.25,3.89 129.88,3.26 U4.8 133.35,3.26 133.6,3.01 133.6,2.29 133.28,1.96 U4.6
N367140: length 28.7
  TOP w0.254: v1(118.36,20.07) 117.74,19.45 U5.3 ; v1(136.65,21.34) 136.65,22.02 136.99,22.35 139.41,22.35 139.71,22.05 R11.2 R9.2 140.7,20.09 C36.2
  LAYER_3 w0.254: v1(136.65,21.34) 135.64,22.35 120.65,22.35 v1(118.36,20.07)
N367168: length 4.1
  TOP w0.254: R12.1 113.27,21.3 113.86,20.71 113.97,20.71 114.82,19.85 R10.2 115.1,20.1 U5.2
N370101: length 3.6
  BOTTOM w0.635: C33.1 141.48,12.19 140.4,12.19 U2.5
N387715: length 2.4
  BOTTOM w0.635: R1.2 JP1.1
N388314: length 2
  BOTTOM w0.635: R72.2 JP1.3
N392987: length 1.7
  TOP w0.381: R14.2 D2.2
N392991: length 1.7
  TOP w0.381: D1.2 R13.2
N402358: length 21.4
  TOP w0.254: R21.2 R19.2 129.54,20.82 C41.2 131.81,19.57 v1(132.08,19.3) ; U5.5 117.3,18.15 117.67,17.78 v1(118.36,17.78)
  LAYER_3 w0.254: v1(132.08,19.3) 131.57,18.8 119.38,18.8 v1(118.36,17.78)
N402362: length 4.1
  TOP w0.254: U5.6 115.1,17.5 R20.2 114.82,17.74 114.23,17.15 114.13,17.15 113.27,16.29 R22.1
N403154: length 26.4
  TOP w0.254: U5.10 120.76,18.15 v1(120.4,17.78) ; v1(103.89,19.81) 104.38,19.32 C43.2 107.44,20.56 R25.2 R27.2
  LAYER_3 w0.254: v1(120.4,17.78) 119.72,17.78 118.95,17.02 117.35,17.02 114.3,20.07 104.82,20.07 104.57,19.81 v1(103.89,19.81)
N403158: length 4.1
  TOP w0.254: R28.1 125.49,16.29 124.9,16.89 124.79,16.89 123.94,17.74 R26.2 123.18,17.78 122.9,17.5 U5.9
N403978: length 29.6
  TOP w0.254: v1(103.12,21.34) 103.12,20.57 101.87,19.32 C45.2 98.55,20.56 R31.2 R33.2 ; U5.12 121.27,19.45 v1(120.4,20.32)
  LAYER_3 w0.254: v1(103.12,21.34) 103.8,21.34 104.06,21.59 114.55,21.59 117.27,18.88 118.65,18.88 120.09,20.32 v1(120.4,20.32)
N403982: length 4.1
  TOP w0.254: U5.13 123.66,20.1 R32.2 123.94,19.85 124.79,20.71 124.9,20.71 125.49,21.3 R34.1
N404826: length 28.1
  TOP w0.254: v1(78.49,19.3) 78.75,19.57 C47.2 79.76,20.82 R37.2 R39.2 ; U6.3 55.76,19.3 v1(57.4,19.3)
  LAYER_3 w0.254: v1(57.4,19.3) 58.42,18.29 61.21,18.29 62.74,19.81 77.98,19.81 v1(78.49,19.3)
N404830: length 4.4
  TOP w0.254: U6.2 54.54,20.1 54.51,20.07 54.1,20.07 53.85,19.81 R38.2 53.61,19.85 52.75,20.71 52.65,20.71 52.06,21.3 R40.1
N405710: length 27.8
  TOP w0.254: R45.2 R43.2 70.36,20.82 C49.2 72.12,19.57 72.39,19.3 73.41,19.3 v1(73.91,18.8) ; v1(58.42,15.75) 57.91,16.26 57.91,17.1 56.87,18.15 U6.5
  LAYER_3 w0.254: v1(58.42,15.75) 71.55,15.75 73.91,18.12 v1(73.91,18.8)
N405714: length 4.3
  TOP w0.254: R46.1 52.06,16.04 52.65,16.63 52.75,16.63 53.61,17.49 R44.2 54.51,17.53 54.54,17.5 U6.6
N406610: length 19.6
  TOP w0.254: v1(59.44,17.27) 59.44,17.95 59.63,18.15 U6.10 ; v1(47.24,18.8) 47.24,19.01 46.69,19.57 C51.2 45.97,20.82 R49.2 R51.2
  LAYER_3 w0.254: v1(59.44,17.27) 52.32,17.27 51.31,18.29 47.75,18.29 v1(47.24,18.8)
N406614: length 4.4
  TOP w0.254: U6.9 62.95,17.5 R50.2 63.23,17.74 64.09,16.89 64.19,16.89 64.78,16.29 R52.1
N407827: length 27.5
  TOP w0.254: U6.12 60.31,19.45 v1(59.44,20.32) ; v1(42.16,17.02) 42.16,17.78 40.96,18.98 40.51,18.98 39.92,19.57 C53.2 39.88,20.82 R55.2 R57.2
  LAYER_3 w0.254: v1(59.44,20.32) 59.18,20.07 44.45,20.07 42.16,17.78 v1(42.16,17.02)
N407831: length 4.4
  TOP w0.254: U6.13 62.95,20.1 R56.2 63.23,19.85 64.09,20.71 64.19,20.71 64.78,21.3 R58.1
N416291: length 2.4
  BOTTOM w0.635: JP2.1 R59.2
N416303: length 2.3
  BOTTOM w0.635: JP2.3 R73.2
N416911: length 2.4
  BOTTOM w0.635: R61.2 JP3.1
N416923: length 2.3
  BOTTOM w0.635: R74.2 JP3.3
N417886: length 2.4
  BOTTOM w0.635: R63.2 JP4.1
N417898: length 2.3
  BOTTOM w0.635: R75.2 JP4.3
N420263: length 2.4
  BOTTOM w0.635: R65.2 JP5.1
N420287: length 2.3
  BOTTOM w0.635: R76.2 JP5.3
N420898: length 2.4
  BOTTOM w0.635: R67.2 JP6.1
N420922: length 2.3
  BOTTOM w0.635: R77.2 JP6.3
N421540: length 2.4
  BOTTOM w0.635: R69.2 JP7.1
N421564: length 2.3
  BOTTOM w0.635: R78.2 JP7.3
N422187: length 3.4
  BOTTOM w0.635: R71.2 34.8,22.86 JP8.1
N422211: length 3.1
  BOTTOM w0.635: JP8.3 39.62,23.11 R79.2

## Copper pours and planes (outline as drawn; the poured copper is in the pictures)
+15V on TOP: 146.05,7.11 145.54,7.11 143,9.65 143,10.16 146.05,13.21 146.05,18.54 146.81,19.3 149.35,19.3 150.11,18.54 150.11,11.18
+15V on TOP: 149.35,15.49 146.81,15.49 146.05,16.26 146.05,32.77 145.54,33.27 135.38,33.27 134.62,32.51 134.62,29.46 134.11,28.96 130.05,28.96 129.79,29.21 129.79,32.77 129.54,33.02 119.89,33.02 119.38,32.51 119.38,29.46 118.87,28.96 115.06,28.96 114.3,29.72 114.3,32.51 113.79,33.02 104.65,33.02 104.14,32.51 104.14,29.97 103.63,29.46 99.31,29.46 98.81,29.97 98.81,32.51 98.3,33.02 89.41,33.02 88.9,32.51 88.9,29.97 88.39,29.46 84.33,29.46 83.82,29.97 83.82,32.51 83.31,33.02 74.42,33.02 73.66,32.26 73.66,30.23 73.15,29.72 68.83,29.72 68.58,29.97 68.58,32.26 68.07,32.77 58.93,32.77 58.42,32.26 58.42,30.23 57.91,29.72 53.85,29.72 53.09,30.48 53.09,32.26 52.58,32.77 43.69,32.77 43.18,32.26 43.18,29.97 42.67,29.46 38.35,29.46 37.85,29.97 37.85,36.58 38.61,37.34 149.1,37.34 150.11,36.32 150.11,16.26
-15V on TOP: 165.35,26.42 165.35,26.92 162.81,29.46 162.31,29.46 159.26,26.42 153.92,26.42 152.91,25.4 152.91,23.37 153.67,22.61 161.54,22.61
-15V on BOTTOM: 32.77,29.46 28.45,29.46 27.94,29.97 27.94,36.83 28.45,37.34 155.19,37.34 157.23,35.31 157.23,23.37 156.46,22.61 153.67,22.61 152.91,23.37 152.91,30.99 150.62,33.27 140.21,33.27 139.7,32.77 139.7,29.46 139.19,28.96 135.13,28.96 134.62,29.46 134.62,32.51 134.11,33.02 124.97,33.02 124.46,32.51 124.46,29.46 123.95,28.96 119.89,28.96 119.38,29.46 119.38,32.51 118.87,33.02 109.73,33.02 109.22,32.51 109.22,29.97 108.71,29.46 104.65,29.46 104.14,29.97 104.14,32.51 103.63,33.02 94.49,33.02 93.98,32.51 93.98,29.97 93.47,29.46 89.41,29.46 88.9,29.97 88.9,32.51 88.39,33.02 79.25,33.02 78.74,32.51 78.74,30.23 78.23,29.72 74.17,29.72 73.66,30.23 73.66,32.26 73.15,32.77 64.01,32.77 63.5,32.26 63.5,30.23 62.99,29.72 58.93,29.72 58.42,30.23 58.42,32.26 57.91,32.77 48.77,32.77 48.26,32.26 48.26,29.97 47.75,29.46 43.69,29.46 43.18,29.97 43.18,32.26 42.67,32.77 33.78,32.77 33.27,32.26 33.27,29.97
GND on LAYER_2: 38.1,0.76 139.7,0.76 164.59,25.65 164.59,37.34 13.21,37.34 13.21,25.65

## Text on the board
Ref Des/Silkscreen Top: -15V|M7|+15V | UCB_VI_v1.0a | 9Jan2018 | Chris Farnell | Ser# | -15V|M6|+15V | -15V|M5|+15V | -15V|M4|+15V | -15V|M3|+15V | -15V|M2|+15V | -15V|M1|+15V | -15V|M0|+15V | +15V | +15V GND -15V | -15V
